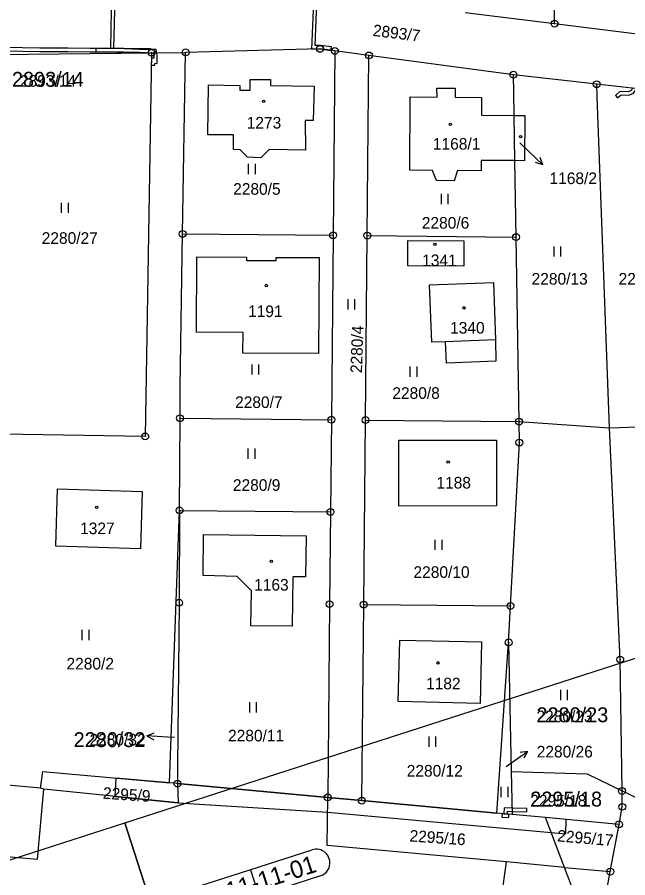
# Model space of a CAD drawing. Extents: x -758836 to -757729, y -1175316 to -1174366.
# Drawn here: x -758433.4 to -758343.9, y -1174763.3 to -1174637.3 of the extents above; entities that cross this region are included whole.
import ezdxf

# ---------------------------------------------------------------- set-up
doc = ezdxf.new("R2010")
doc.units = 0
for name, color, linetype in [('_NOR-pomocná', 7, 'Continuous'), ('_NOR-popis', 7, 'Continuous'), ('Hranice parcel', 7, 'Continuous'), ('Parcelní čísla', 7, 'Continuous'), ('Pop  PČ popisy', 7, 'Continuous'), ('Vnitřní kresba', 7, 'Continuous'), ('Věcná břemena k části', 7, 'Continuous'), ('Značky bodu BP', 7, 'Continuous'), ('Značky budov', 7, 'Continuous'), ('Značky kultur', 7, 'Continuous')]:
    doc.layers.add(name, color=color, linetype=linetype)

msp = doc.modelspace()

# ---------------------------------------------------------------- linework, layer by layer
at = {"layer": '_NOR-pomocná'}
msp.add_line((-758399.22, -1174762.1), (-758398, -1174765.9), dxfattribs=at)
for points in [[(-758417.59, -1174755.22), (-758317.65, -1174723.03), (-758272.12, -1174864.38), (-758372.07, -1174896.57)], [(-758517.54, -1174787.42), (-758417.59, -1174755.22), (-758372.07, -1174896.57), (-758472.01, -1174928.76)]]:
    msp.add_lwpolyline(points, close=True, dxfattribs=at)
at = {"layer": '_NOR-popis'}
for points in [[(-758408.27, -1174765.01), (-758390.18, -1174759.18)], [(-758388.95, -1174762.99), (-758398, -1174765.9), (-758378.82, -1174825.45)]]:
    msp.add_lwpolyline(points, dxfattribs=at)
msp.add_arc((-758389.57, -1174761.09), 2, 287.8533, 107.854, dxfattribs=at)
at = {"layer": 'Hranice parcel'}
for p, q in [((-758354.67, -1174638.23), (-758355.96, -1174575.06)), ((-758367.77, -1174636.6), (-758354.67, -1174638.23)), ((-758354.67, -1174638.23), (-758342.58, -1174639.74)), ((-758438.13, -1174642.79), (-758413.7, -1174642.5)), ((-758413.7, -1174642.5), (-758414.62, -1174698.66)), ((-758413.7, -1174642.5), (-758408.7, -1174642.44)), ((-758409.14, -1174669.01), (-758408.7, -1174642.44)), ((-758386.84, -1174642.22), (-758387.1, -1174669.22)), ((-758381.85, -1174642.89), (-758386.84, -1174642.22)), ((-758382.1, -1174669.27), (-758381.85, -1174642.89)), ((-758360.69, -1174645.71), (-758381.85, -1174642.89)), ((-758348.5, -1174647.1), (-758360.69, -1174645.71)), ((-758342.92, -1174647.74), (-758348.5, -1174647.1)), ((-758360.49, -1174658.29), (-758360.6, -1174651.67)), ((-758360.31, -1174669.48), (-758360.49, -1174658.29)), ((-758409.14, -1174669.01), (-758387.1, -1174669.22)), ((-758387.1, -1174669.22), (-758387.36, -1174696.22)), ((-758382.36, -1174696.27), (-758382.1, -1174669.27)), ((-758382.1, -1174669.27), (-758360.31, -1174669.48)), ((-758359.87, -1174696.48), (-758360.31, -1174669.48)), ((-758409.59, -1174709.5), (-758409.52, -1174696)), ((-758409.52, -1174696), (-758387.36, -1174696.22)), ((-758387.36, -1174696.22), (-758387.49, -1174709.72)), ((-758382.62, -1174723.27), (-758382.36, -1174696.27)), ((-758382.36, -1174696.27), (-758359.87, -1174696.48)), ((-758359.87, -1174696.48), (-758346.61, -1174697.42)), ((-758346.61, -1174697.42), (-758335.32, -1174696.99)), ((-758414.62, -1174698.66), (-758435.54, -1174698.32)), ((-758411.05, -1174749.38), (-758409.59, -1174709.5)), ((-758409.59, -1174709.5), (-758387.49, -1174709.72)), ((-758382.9, -1174751.98), (-758382.62, -1174723.27)), ((-758382.62, -1174723.27), (-758361.11, -1174723.47)), ((-758361.4, -1174728.81), (-758361.11, -1174723.47)), ((-758363.13, -1174753.8), (-758361.4, -1174728.81)), ((-758361.4, -1174728.81), (-758361.02, -1174747.72)), ((-758361.02, -1174747.72), (-758360.89, -1174754.01)), ((-758429.95, -1174750.16), (-758435.29, -1174749.65)), ((-758409.9, -1174749.48), (-758411.05, -1174749.38)), ((-758409.9, -1174749.48), (-758387.89, -1174751.51)), ((-758429.49, -1174750.29), (-758429.95, -1174750.16)), ((-758387.96, -1174758.53), (-758387.89, -1174751.51)), ((-758387.89, -1174751.51), (-758382.9, -1174751.98)), ((-758382.9, -1174751.98), (-758363.13, -1174753.8)), ((-758360.89, -1174754.01), (-758363.13, -1174753.8)), ((-758356.02, -1174754.46), (-758360.89, -1174754.01)), ((-758353.2, -1174761.75), (-758356.02, -1174754.46)), ((-758345.23, -1174755.46), (-758356.02, -1174754.46)), ((-758346.51, -1174762.37), (-758345.23, -1174755.46)), ((-758361.69, -1174760.96), (-758387.96, -1174758.53)), ((-758363.58, -1174773.76), (-758361.69, -1174760.96)), ((-758353.2, -1174761.75), (-758361.69, -1174760.96)), ((-758353.2, -1174761.75), (-758346.51, -1174762.37)), ((-758349.61, -1174779.02), (-758346.51, -1174762.37))]:
    msp.add_line(p, q, dxfattribs=at)
for points in [[(-758386.84, -1174642.22), (-758389.02, -1174641.93), (-758408.7, -1174642.44)], [(-758396.28, -1174646.41), (-758396.27, -1174647.3), (-758389.86, -1174647.38), (-758390, -1174652.41), (-758391.19, -1174652.41), (-758391.17, -1174656.75), (-758396.49, -1174656.68), (-758397.7, -1174657.89), (-758399.64, -1174657.78), (-758400.71, -1174656.69), (-758401.69, -1174656.68), (-758401.68, -1174654.49), (-758405.46, -1174654.5), (-758405.36, -1174647.21), (-758400.75, -1174647.27), (-758400.76, -1174647.97), (-758399.25, -1174647.98), (-758399.24, -1174646.39), (-758396.28, -1174646.41)], [(-758360.6, -1174651.67), (-758360.65, -1174648.31), (-758360.69, -1174645.71)], [(-758360.49, -1174658.29), (-758365.4, -1174658.26), (-758365.41, -1174659.77), (-758368.86, -1174659.75), (-758369.38, -1174661.24), (-758371.96, -1174661.21), (-758372.54, -1174659.73), (-758375.85, -1174659.7), (-758375.81, -1174648.94), (-758371.88, -1174648.98), (-758371.89, -1174647.69), (-758369.24, -1174647.7), (-758369.24, -1174649), (-758365.35, -1174649.03), (-758365.37, -1174651.63), (-758360.6, -1174651.67)], [(-758346.61, -1174697.42), (-758348.43, -1174648.94), (-758348.5, -1174647.1)], [(-758360.6, -1174651.67), (-758359.03, -1174651.68), (-758359.07, -1174658.3), (-758360.49, -1174658.29)], [(-758409.52, -1174696), (-758409.5, -1174691.51), (-758409.14, -1174669.01)], [(-758376.18, -1174673.69), (-758376.17, -1174669.97), (-758367.96, -1174670.04), (-758367.96, -1174673.74), (-758376.18, -1174673.69)], [(-758399.78, -1174672.4), (-758399.77, -1174672.92), (-758395.44, -1174672.93), (-758395.43, -1174672.45), (-758389.14, -1174672.47), (-758389.22, -1174686.54), (-758400.3, -1174686.45), (-758400.28, -1174683.45), (-758407.11, -1174683.39), (-758407.06, -1174672.37), (-758399.78, -1174672.4)], [(-758363.59, -1174676.12), (-758363.3, -1174684.53), (-758363.25, -1174687.66), (-758370.5, -1174687.93), (-758370.66, -1174684.8), (-758372.66, -1174684.86), (-758372.97, -1174676.48), (-758363.59, -1174676.12)], [(-758361.11, -1174723.47), (-758359.82, -1174699.56), (-758359.87, -1174696.48)], [(-758344.78, -1174750.56), (-758345.05, -1174731.32), (-758346.61, -1174697.42)], [(-758363.16, -1174699.19), (-758363.15, -1174708.8), (-758377.47, -1174708.85), (-758377.5, -1174699.23), (-758363.16, -1174699.19)], [(-758415.33, -1174715.11), (-758427.71, -1174714.73), (-758427.46, -1174706.34), (-758415.07, -1174706.71), (-758415.33, -1174715.11)], [(-758409.59, -1174709.5), (-758409.65, -1174723), (-758409.88, -1174746.98), (-758409.9, -1174749.48)], [(-758387.49, -1174709.72), (-758387.62, -1174723.22), (-758387.89, -1174751.51)], [(-758399.13, -1174726.37), (-758399.05, -1174721.25), (-758401.16, -1174719.15), (-758406.15, -1174719.02), (-758406.07, -1174713.02), (-758391.05, -1174713.22), (-758391.13, -1174719.22), (-758393.01, -1174719.21), (-758393.11, -1174726.43), (-758399.13, -1174726.37)], [(-758377.57, -1174737.45), (-758377.35, -1174728.49), (-758365.35, -1174728.74), (-758365.55, -1174737.75), (-758377.57, -1174737.45)], [(-758461.07, -1174747.52), (-758461.94, -1174757.82), (-758430.38, -1174760.57), (-758429.49, -1174750.29)], [(-758429.95, -1174750.16), (-758429.61, -1174747.73), (-758411.05, -1174749.38)], [(-758361.02, -1174747.72), (-758349.91, -1174748.04), (-758344.78, -1174750.56)], [(-758409.9, -1174749.48), (-758409.78, -1174752.31), (-758429.49, -1174750.29)], [(-758345.23, -1174755.46), (-758344.75, -1174752.89), (-758344.78, -1174750.56)], [(-758333.29, -1174766.74), (-758339.51, -1174753.16), (-758344.78, -1174750.56)], [(-758363.58, -1174773.76), (-758351.79, -1174765.46), (-758353.2, -1174761.75)]]:
    msp.add_lwpolyline(points, dxfattribs=at)
at = {"layer": 'Pop  PČ popisy'}
for p, q in [((-758359.76, -1174655.66), (-758358.57, -1174656.81)), ((-758358.57, -1174656.81), (-758356.41, -1174658.9)), ((-758356.41, -1174658.9), (-758356.78, -1174657.84)), ((-758356.41, -1174658.9), (-758357.48, -1174658.56)), ((-758414.36, -1174742.51), (-758413.33, -1174742.06)), ((-758411.36, -1174742.67), (-758414.36, -1174742.51)), ((-758414.36, -1174742.51), (-758413.38, -1174743.06)), ((-758410.32, -1174742.72), (-758411.36, -1174742.67)), ((-758361.07, -1174746.5), (-758358.61, -1174744.78)), ((-758358.61, -1174744.78), (-758359.72, -1174744.94)), ((-758358.61, -1174744.78), (-758359.15, -1174745.76)), ((-758361.77, -1174747), (-758361.07, -1174746.5))]:
    msp.add_line(p, q, dxfattribs=at)
at = {"layer": 'Vnitřní kresba'}
msp.add_line((-758363.3, -1174684.53), (-758370.66, -1174684.8), dxfattribs=at)
at = {"layer": 'Věcná břemena k části'}
for points in [[(-758389.42, -1174633.93), (-758389.77, -1174633.94), (-758389.93, -1174633.94), (-758390.26, -1174641.96), (-758389.02, -1174641.93), (-758387.42, -1174642.14), (-758387.35, -1174641.64), (-758388.96, -1174641.43), (-758389.74, -1174641.45)], [(-758415.25, -1174642.52), (-758413.7, -1174642.5), (-758413.43, -1174642.5), (-758412.93, -1174642.49), (-758413.02, -1174642), (-758415.49, -1174642.01), (-758418.8, -1174641.89), (-758421.85, -1174641.86), (-758421.87, -1174642.36), (-758418.8, -1174642.39)], [(-758412.93, -1174642.49), (-758413.43, -1174642.5), (-758413.35, -1174642.92), (-758413.36, -1174643.3), (-758413.71, -1174643.29), (-758413.73, -1174644.29), (-758413.23, -1174644.3), (-758413.22, -1174644.05), (-758412.89, -1174644.01), (-758412.85, -1174642.89)], [(-758344.93, -1174648.67), (-758343.77, -1174648.72), (-758343.1, -1174648.42), (-758342.69, -1174647.79), (-758342.92, -1174647.74), (-758343.27, -1174647.7), (-758343.46, -1174648.04), (-758343.87, -1174648.22), (-758345.11, -1174648.17), (-758345.76, -1174648.74), (-758345.43, -1174649.11)], [(-758352.97, -1174754.74), (-758356.02, -1174754.46), (-758360.89, -1174754.01), (-758363.13, -1174753.8), (-758382.9, -1174751.98), (-758387.89, -1174751.51), (-758409.9, -1174749.48), (-758411.05, -1174749.38), (-758418.92, -1174748.68), (-758419.06, -1174751.36), (-758409.78, -1174752.31), (-758387.91, -1174753.68), (-758355.17, -1174756.65), (-758353.01, -1174756.82)], [(-758362.1, -1174753.9), (-758361.6, -1174753.94), (-758361.58, -1174753.53), (-758360.9, -1174753.56), (-758358.73, -1174753.64), (-758358.71, -1174753.14), (-758360.91, -1174753.06), (-758362.04, -1174753.01)], [(-758362.38, -1174754.38), (-758361.39, -1174754.46), (-758361.35, -1174753.97), (-758361.6, -1174753.94), (-758362.1, -1174753.9), (-758362.34, -1174753.88)]]:
    msp.add_lwpolyline(points, close=True, dxfattribs=at)
for points in [[(-758419.59, -1174636.22), (-758419.71, -1174641.86), (-758422.7, -1174641.85), (-758425.92, -1174641.8), (-758430.05, -1174641.8), (-758435.18, -1174641.73)], [(-758435.18, -1174642.23), (-758430.05, -1174642.3), (-758425.92, -1174642.3), (-758422.7, -1174642.35), (-758419.47, -1174642.36), (-758417.82, -1174642.36), (-758415.46, -1174642.4), (-758413.7, -1174642.5), (-758413.1, -1174642.49), (-758413.17, -1174642.26), (-758413.84, -1174641.93), (-758415.46, -1174641.9), (-758417.82, -1174641.86), (-758419.21, -1174641.86), (-758419.09, -1174636.24)]]:
    msp.add_lwpolyline(points, dxfattribs=at)
at = {"layer": 'Značky bodu BP'}
for centre, radius in [((-758354.67, -1174638.23), 0.5), ((-758354.67, -1174638.23), 0.0303), ((-758389.02, -1174641.93), 0.5), ((-758413.7, -1174642.5), 0.5), ((-758413.7, -1174642.5), 0.0303), ((-758408.7, -1174642.44), 0.5), ((-758408.7, -1174642.44), 0.0303), ((-758389.02, -1174641.93), 0.0303), ((-758386.84, -1174642.22), 0.5), ((-758386.84, -1174642.22), 0.0303), ((-758381.85, -1174642.89), 0.5), ((-758381.85, -1174642.89), 0.0303), ((-758360.69, -1174645.71), 0.5), ((-758360.69, -1174645.71), 0.0303), ((-758348.5, -1174647.1), 0.5), ((-758348.5, -1174647.1), 0.0303), ((-758409.14, -1174669.01), 0.5), ((-758409.14, -1174669.01), 0.0303), ((-758387.1, -1174669.22), 0.5), ((-758387.1, -1174669.22), 0.0303), ((-758382.1, -1174669.27), 0.5), ((-758382.1, -1174669.27), 0.0303), ((-758360.31, -1174669.48), 0.5), ((-758360.31, -1174669.48), 0.0303), ((-758409.52, -1174696), 0.5), ((-758387.36, -1174696.22), 0.5), ((-758409.52, -1174696), 0.0303), ((-758387.36, -1174696.22), 0.0303), ((-758382.36, -1174696.27), 0.5), ((-758382.36, -1174696.27), 0.0303), ((-758359.87, -1174696.48), 0.5), ((-758359.87, -1174696.48), 0.0303), ((-758414.62, -1174698.66), 0.5), ((-758414.62, -1174698.66), 0.0303), ((-758359.82, -1174699.56), 0.5), ((-758359.82, -1174699.56), 0.0303), ((-758409.59, -1174709.5), 0.5), ((-758409.59, -1174709.5), 0.0303), ((-758387.49, -1174709.72), 0.5), ((-758387.49, -1174709.72), 0.0303), ((-758409.65, -1174723), 0.5), ((-758409.65, -1174723), 0.0303), ((-758387.62, -1174723.22), 0.5), ((-758387.62, -1174723.22), 0.0303), ((-758382.62, -1174723.27), 0.5), ((-758382.62, -1174723.27), 0.0303), ((-758361.11, -1174723.47), 0.5), ((-758361.11, -1174723.47), 0.0303), ((-758361.4, -1174728.81), 0.5), ((-758361.4, -1174728.81), 0.0303), ((-758345.05, -1174731.32), 0.5), ((-758345.05, -1174731.32), 0.0303), ((-758409.9, -1174749.48), 0.5), ((-758409.9, -1174749.48), 0.0303), ((-758387.89, -1174751.51), 0.5), ((-758344.78, -1174750.56), 0.5), ((-758344.78, -1174750.56), 0.0303), ((-758387.89, -1174751.51), 0.0303), ((-758382.9, -1174751.98), 0.5), ((-758382.9, -1174751.98), 0.0303), ((-758344.75, -1174752.89), 0.5), ((-758344.75, -1174752.89), 0.0303), ((-758345.23, -1174755.46), 0.5), ((-758345.23, -1174755.46), 0.0303), ((-758346.51, -1174762.37), 0.5), ((-758346.51, -1174762.37), 0.0303)]:
    msp.add_circle(centre, radius, dxfattribs=at)
at = {"layer": 'Značky budov'}
for centre in [(-758397.29, -1174649.59), (-758369.92, -1174652.96), (-758359.65, -1174654.78), (-758372.16, -1174670.54), (-758396.9, -1174676.57), (-758367.95, -1174679.84), (-758370.25, -1174702.41), (-758421.73, -1174709.06), (-758396.17, -1174716.96), (-758371.75, -1174731.81)]:
    msp.add_circle(centre, 0.175, dxfattribs=at)
at = {"layer": 'Značky kultur'}
for p, q in [((-758399.47, -1174660.27), (-758399.47, -1174658.77)), ((-758398.47, -1174660.27), (-758398.47, -1174658.77)), ((-758371.23, -1174664.67), (-758371.23, -1174663.17)), ((-758370.23, -1174664.67), (-758370.23, -1174663.17)), ((-758426.88, -1174665.95), (-758426.88, -1174664.45)), ((-758425.88, -1174665.95), (-758425.88, -1174664.45)), ((-758354.75, -1174672.34), (-758354.75, -1174670.84)), ((-758353.75, -1174672.34), (-758353.75, -1174670.84)), ((-758384.91, -1174680.06), (-758384.91, -1174678.56)), ((-758383.91, -1174680.06), (-758383.91, -1174678.56)), ((-758398.97, -1174689.61), (-758398.97, -1174688.11)), ((-758397.97, -1174689.61), (-758397.97, -1174688.11)), ((-758375.81, -1174689.93), (-758375.81, -1174688.43)), ((-758374.81, -1174689.93), (-758374.81, -1174688.43)), ((-758399.54, -1174701.94), (-758399.54, -1174700.44)), ((-758398.54, -1174701.94), (-758398.54, -1174700.44)), ((-758372.15, -1174715.28), (-758372.15, -1174713.78)), ((-758371.15, -1174715.28), (-758371.15, -1174713.78)), ((-758423.84, -1174728.5), (-758423.84, -1174727)), ((-758422.84, -1174728.5), (-758422.84, -1174727)), ((-758353.75, -1174737.26), (-758353.75, -1174735.76)), ((-758352.75, -1174737.26), (-758352.75, -1174735.76)), ((-758399.3, -1174739.08), (-758399.3, -1174737.58)), ((-758398.3, -1174739.08), (-758398.3, -1174737.58)), ((-758373.05, -1174744.1), (-758373.05, -1174742.6)), ((-758372.05, -1174744.1), (-758372.05, -1174742.6)), ((-758362.47, -1174751.46), (-758362.47, -1174749.96)), ((-758361.47, -1174751.46), (-758361.47, -1174749.96))]:
    msp.add_line(p, q, dxfattribs=at)

# ---------------------------------------------------------------- texts
at = {"layer": '_NOR-popis'}
msp.add_text('SO 11-11-01', height=2.5468, rotation=17.854, dxfattribs=at).set_placement((-758407.91, -1174768.33))
at = {"layer": 'Parcelní čísla'}
for s, rotation, p in [('2893/7', 353, (-758381.36, -1174640.02)), ('2280/4', 88, (-758382.88, -1174689.42)), ('2295/9', 356, (-758420.86, -1174751.69)), ('2295/16', 356, (-758375.95, -1174757.95)), ('2295/17', 355, (-758354.33, -1174757.94))]:
    msp.add_text(s, height=1.7, rotation=rotation, dxfattribs=at).set_placement(p)
for s, height, p in [('2893/14', 2.175, (-758434.14, -1174647.47)), ('2893/14', 1.7, (-758432.97, -1174647.47)), ('1273', 1.7, (-758399.76, -1174653.59)), ('1168/1', 1.7, (-758372.49, -1174656.68)), ('1168/2', 1.7, (-758355.41, -1174661.72)), ('2280/5', 1.7, (-758401.74, -1174663.28)), ('2280/6', 1.7, (-758374.11, -1174668.24)), ('2280/27', 1.7, (-758429.78, -1174670.47)), ('1341', 1.7, (-758374.06, -1174673.73)), ('2280/13', 1.7, (-758358.03, -1174676.44)), ('2280/15', 1.7, (-758345.29, -1174676.44)), ('1191', 1.7, (-758399.56, -1174681.19)), ('1340', 1.7, (-758369.97, -1174683.61)), ('2280/8', 1.7, (-758378.43, -1174693.16)), ('2280/7', 1.7, (-758401.46, -1174694.5)), ('2280/9', 1.7, (-758401.78, -1174706.63)), ('1188', 1.7, (-758371.97, -1174706.29)), ('1327', 1.7, (-758424.16, -1174712.97)), ('2280/10', 1.7, (-758375.33, -1174719.37)), ('1163', 1.7, (-758398.67, -1174721.23)), ('2280/2', 1.7, (-758426.15, -1174732.78)), ('1182', 1.7, (-758373.49, -1174735.69)), ('2280/23', 2.175, (-758357.32, -1174740.5)), ('2280/23', 1.7, (-758357.32, -1174740.5)), ('2280/32', 2.175, (-758425.11, -1174744.14)), ('2280/32', 1.7, (-758422.78, -1174743.91)), ('2280/11', 1.7, (-758402.49, -1174743.31)), ('2280/26', 1.7, (-758357.28, -1174745.66)), ('2280/12', 1.7, (-758376.32, -1174748.46)), ('2295/18', 1.7, (-758358.23, -1174752.84)), ('2295/18', 2.175, (-758358.23, -1174752.84))]:
    msp.add_text(s, height=height, dxfattribs=at).set_placement(p)

doc.saveas('drawing.dxf')
